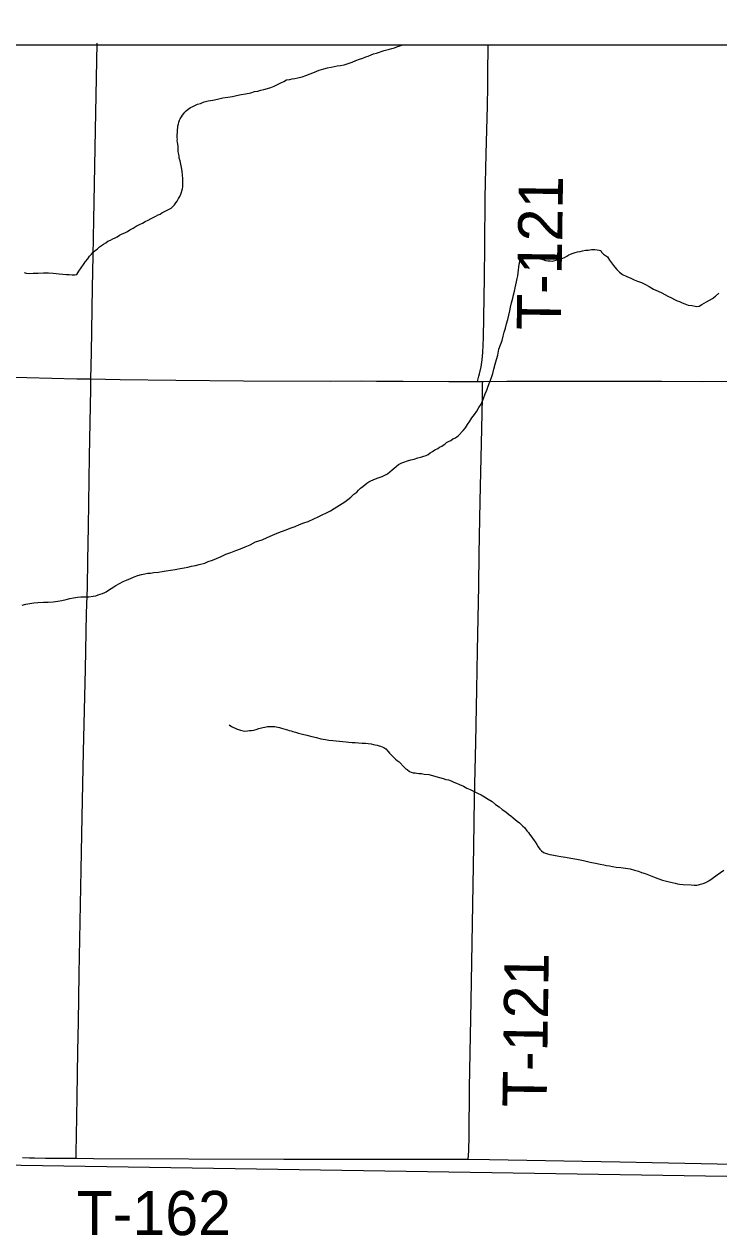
# Model space of a CAD drawing. Extents: x 2.1 to 73.9, y 4 to 26.
# Drawn here: x 44.021 to 44.468, y 18.775 to 19.554 of the extents above; entities that cross this region are included whole.
import ezdxf

# ---------------------------------------------------------------- set-up
doc = ezdxf.new("R2010")
doc.units = 0
for name, color, linetype in [('GM_X_Minor_River', 7, 'Continuous'), ('GM_X_Township_Road', 7, 'Continuous'), ('GM_X_Township_Road_Text', 7, 'Continuous'), ('SH_Text', 7, 'Continuous')]:
    doc.layers.add(name, color=color, linetype=linetype)

msp = doc.modelspace()

# ---------------------------------------------------------------- linework, layer by layer
at = {"layer": 'GM_X_Minor_River'}
for points in [[(44.25604, 19.53844), (44.25757, 19.53878), (44.25929, 19.53932), (44.26082, 19.53985), (44.26274, 19.54057), (44.26385, 19.54109), (44.26385, 19.54109)], [(44.11396, 19.4353), (44.11551, 19.43621), (44.11687, 19.43751), (44.11765, 19.43844), (44.11862, 19.43956), (44.11941, 19.44068), (44.1204, 19.44237), (44.12119, 19.44368), (44.12179, 19.44519), (44.12282, 19.44858), (44.12304, 19.44991), (44.12308, 19.45161), (44.12312, 19.45332), (44.12316, 19.45522), (44.12283, 19.45732), (44.1227, 19.45998), (44.12218, 19.46227), (44.12185, 19.46456), (44.12133, 19.46666), (44.1208, 19.46838), (44.12064, 19.4699), (44.1203, 19.47162), (44.12014, 19.47295), (44.11999, 19.47447), (44.12002, 19.4758), (44.11986, 19.47733), (44.1197, 19.47847), (44.11953, 19.47961), (44.11956, 19.48056), (44.11939, 19.48151), (44.11944, 19.4836), (44.11965, 19.48474), (44.11968, 19.48588), (44.1197, 19.48682), (44.11992, 19.48796), (44.11994, 19.4891), (44.12035, 19.49023), (44.12057, 19.49155), (44.12097, 19.49268), (44.12138, 19.49362), (44.12217, 19.49494), (44.12295, 19.49606), (44.12373, 19.49699), (44.12432, 19.49793), (44.1253, 19.49885), (44.12646, 19.49978), (44.128, 19.50088), (44.12916, 19.50143), (44.13243, 19.50306), (44.13453, 19.50358), (44.13683, 19.50448), (44.13932, 19.50518), (44.14237, 19.50568), (44.14543, 19.50637), (44.14887, 19.50706), (44.15211, 19.50755), (44.15497, 19.50806), (44.15765, 19.50857), (44.16051, 19.50926), (44.16338, 19.50977), (44.16681, 19.51045), (44.16911, 19.51116), (44.1714, 19.51148), (44.17331, 19.51201), (44.17523, 19.51254), (44.17752, 19.51306), (44.17963, 19.51377), (44.18174, 19.51467), (44.18404, 19.51576), (44.18616, 19.51685), (44.18808, 19.51775), (44.18981, 19.51867), (44.19191, 19.519), (44.19344, 19.51934), (44.19515, 19.51949), (44.19707, 19.52002), (44.19974, 19.52072), (44.20224, 19.52161), (44.20492, 19.5225), (44.2078, 19.52358), (44.21086, 19.52484), (44.21374, 19.52572), (44.21603, 19.52643), (44.21852, 19.52694), (44.22043, 19.52728), (44.22233, 19.52762), (44.22443, 19.52795), (44.22692, 19.52846), (44.2294, 19.52917), (44.2319, 19.53006), (44.23439, 19.53114), (44.23669, 19.53204), (44.2388, 19.53275), (44.24072, 19.53347), (44.24225, 19.534), (44.24417, 19.53472), (44.24571, 19.53545), (44.24762, 19.53597), (44.2526, 19.53757), (44.25432, 19.53791), (44.25604, 19.53844)], [(44.02103, 19.39486), (44.02235, 19.39445), (44.02425, 19.39421), (44.02692, 19.39434), (44.02996, 19.39446), (44.03338, 19.39458), (44.03661, 19.39451), (44.03965, 19.39444), (44.04345, 19.39397), (44.04591, 19.39372), (44.048, 19.39349), (44.0499, 19.39344), (44.05199, 19.3934), (44.0537, 19.39336), (44.05484, 19.39352), (44.05622, 19.39558), (44.05779, 19.39782), (44.05917, 19.39988), (44.06055, 19.40194), (44.06192, 19.40362), (44.06309, 19.4053), (44.06426, 19.4066), (44.06543, 19.40791), (44.06679, 19.40902), (44.06815, 19.41012), (44.0695, 19.41123), (44.07066, 19.41216), (44.07202, 19.41308), (44.07356, 19.41399), (44.07491, 19.41491), (44.07645, 19.41563), (44.07799, 19.41655), (44.07952, 19.41708), (44.08087, 19.41781), (44.08241, 19.41873), (44.08414, 19.41964), (44.08587, 19.42036), (44.08741, 19.42127), (44.08895, 19.42219), (44.09107, 19.42328), (44.093, 19.42457), (44.09512, 19.42566), (44.09704, 19.42656), (44.09877, 19.42766), (44.10069, 19.42857), (44.10262, 19.42948), (44.10435, 19.43039), (44.10569, 19.43112), (44.10723, 19.43184), (44.10858, 19.43238), (44.10954, 19.43312), (44.11089, 19.43385), (44.11204, 19.43439), (44.11301, 19.43494), (44.11396, 19.4353)], [(44.26271, 19.27183), (44.26386, 19.27238), (44.26521, 19.27292), (44.26751, 19.27362), (44.2698, 19.27433), (44.27191, 19.27486), (44.2742, 19.27556), (44.27612, 19.27609), (44.27803, 19.27662), (44.27956, 19.27715), (44.28091, 19.27788), (44.28226, 19.2788), (44.28361, 19.27972), (44.28516, 19.28082), (44.28708, 19.28173), (44.28824, 19.28246), (44.28958, 19.28319), (44.29055, 19.28374), (44.29151, 19.28448), (44.29268, 19.2854), (44.29402, 19.28613), (44.29537, 19.28686), (44.29672, 19.28778), (44.29807, 19.28832), (44.29922, 19.28905), (44.30038, 19.28998), (44.3035, 19.29332), (44.30487, 19.295), (44.30625, 19.29706), (44.30763, 19.29912), (44.30901, 19.30137), (44.31058, 19.30342), (44.31215, 19.30566), (44.31353, 19.30791), (44.31491, 19.31016), (44.31651, 19.31373), (44.31753, 19.31675), (44.31854, 19.31919), (44.31954, 19.32164), (44.32056, 19.32447), (44.32157, 19.32729), (44.32239, 19.32993), (44.32322, 19.33276), (44.32405, 19.33578), (44.32488, 19.3388), (44.3257, 19.34163), (44.32636, 19.34542), (44.32737, 19.34824), (44.32839, 19.35107), (44.32902, 19.3539), (44.32984, 19.35654), (44.33066, 19.35899), (44.33129, 19.36183), (44.33212, 19.36466), (44.33275, 19.36749), (44.33338, 19.37014), (44.33382, 19.3726), (44.33445, 19.37524), (44.33528, 19.37826), (44.33571, 19.38053), (44.33633, 19.38279), (44.33676, 19.38487), (44.33719, 19.38695), (44.33761, 19.38884), (44.33804, 19.39092), (44.33846, 19.39262), (44.33869, 19.39452), (44.33893, 19.3966), (44.33916, 19.3983), (44.33939, 19.4002), (44.3398, 19.40171), (44.34003, 19.40322), (44.34043, 19.40435), (44.34141, 19.40547), (44.34294, 19.40601), (44.34389, 19.40579), (44.34522, 19.40557), (44.34654, 19.40536), (44.34787, 19.40514), (44.349, 19.40492), (44.35032, 19.40451), (44.35165, 19.4041), (44.35316, 19.40369), (44.35466, 19.40308), (44.35636, 19.40247), (44.35788, 19.40225), (44.3594, 19.40222), (44.36073, 19.40219), (44.36244, 19.40253), (44.36417, 19.40306), (44.36589, 19.40359), (44.36742, 19.40412), (44.36857, 19.40448), (44.37011, 19.40539), (44.37127, 19.40613), (44.37242, 19.40667), (44.37415, 19.4072), (44.37549, 19.40774), (44.37702, 19.40809), (44.37855, 19.40843), (44.38008, 19.40878)], [(44.38008, 19.40878), (44.38199, 19.40911), (44.38389, 19.40926), (44.38599, 19.40959), (44.38808, 19.40954), (44.38959, 19.40932), (44.39092, 19.4091), (44.39187, 19.40889), (44.39241, 19.40793), (44.39371, 19.40657), (44.39484, 19.40578), (44.39615, 19.4048), (44.39743, 19.40269), (44.40001, 19.3994), (44.40094, 19.39824), (44.40223, 19.39669), (44.40391, 19.39513), (44.40597, 19.39357), (44.40859, 19.39218), (44.41123, 19.39117), (44.41349, 19.39017), (44.41556, 19.38917), (44.4182, 19.38835), (44.42065, 19.38716), (44.42309, 19.38578), (44.4259, 19.38419), (44.42872, 19.3828), (44.43117, 19.3818), (44.43305, 19.38061), (44.43511, 19.37962), (44.43737, 19.37862), (44.43925, 19.37743), (44.44094, 19.37664), (44.44264, 19.37622), (44.44433, 19.37542), (44.44603, 19.37462), (44.4481, 19.37382), (44.45037, 19.37358), (44.45151, 19.37336), (44.45378, 19.37293), (44.45512, 19.37309), (44.45685, 19.37419), (44.45839, 19.3751), (44.45994, 19.37602), (44.46186, 19.37693), (44.46378, 19.37802), (44.46572, 19.3795), (44.46785, 19.38154)], [(44.02208, 19.18155), (44.02475, 19.18187), (44.02724, 19.18239), (44.02991, 19.1827), (44.03352, 19.18281), (44.03656, 19.18293), (44.03961, 19.18305), (44.04266, 19.18356), (44.04533, 19.18387), (44.04801, 19.18457), (44.05049, 19.18509), (44.05278, 19.18561), (44.05527, 19.18612), (44.05755, 19.18626), (44.06021, 19.1862), (44.06269, 19.18633), (44.06535, 19.18665), (44.06707, 19.18699), (44.06861, 19.18753), (44.06994, 19.18788), (44.07148, 19.18841), (44.07282, 19.18895), (44.07378, 19.1895), (44.07533, 19.1906), (44.07707, 19.1917), (44.07861, 19.19262), (44.07996, 19.19354), (44.08477, 19.19609), (44.08688, 19.19699), (44.08938, 19.19807), (44.09187, 19.19916), (44.09417, 19.20005), (44.09647, 19.20057), (44.09857, 19.20109), (44.10048, 19.20143), (44.10238, 19.20158), (44.10448, 19.20191), (44.10734, 19.20203), (44.10982, 19.20255), (44.1123, 19.20287), (44.11516, 19.20338), (44.11821, 19.20388), (44.12127, 19.20438), (44.12394, 19.20489), (44.12623, 19.20541), (44.12871, 19.20592), (44.1312, 19.20643), (44.13369, 19.20714), (44.13713, 19.20801), (44.13943, 19.20891), (44.14211, 19.20979), (44.1448, 19.21087), (44.14768, 19.21214), (44.15075, 19.21359), (44.15401, 19.21484), (44.15708, 19.2161), (44.16015, 19.21717), (44.16322, 19.21843), (44.16629, 19.21969), (44.16975, 19.22152), (44.17416, 19.22294), (44.17742, 19.22438), (44.18068, 19.22583), (44.18375, 19.22709), (44.18664, 19.22835), (44.18951, 19.22943), (44.1922, 19.2305), (44.19526, 19.23157), (44.19814, 19.23284), (44.20083, 19.23392), (44.2037, 19.2348), (44.20735, 19.23643), (44.21004, 19.2377), (44.21273, 19.23897), (44.21542, 19.24024), (44.21811, 19.2415), (44.22042, 19.24297), (44.22718, 19.24738), (44.2293, 19.24885), (44.23124, 19.25032), (44.23299, 19.25218), (44.23492, 19.25366), (44.23609, 19.25477), (44.23745, 19.25607), (44.23881, 19.25718), (44.24016, 19.25829), (44.24152, 19.2594), (44.24268, 19.26013), (44.24402, 19.26086), (44.24556, 19.26159), (44.24709, 19.26212), (44.24882, 19.26284), (44.25131, 19.26355), (44.25304, 19.26446), (44.25477, 19.26537), (44.25632, 19.26666), (44.25768, 19.26796), (44.25904, 19.26907), (44.2602, 19.26999), (44.26175, 19.27129), (44.26271, 19.27183)], [(44.01979, 19.18084), (44.02208, 19.18155)], [(44.15283, 19.10395), (44.15432, 19.10278), (44.15752, 19.10138), (44.16017, 19.10056), (44.16187, 19.10014), (44.163, 19.09993), (44.16472, 19.10008), (44.16586, 19.10024), (44.1672, 19.1004), (44.16872, 19.10056), (44.17025, 19.1009), (44.17198, 19.10162), (44.17446, 19.10213), (44.1758, 19.10248), (44.17752, 19.10283), (44.18227, 19.10291), (44.18322, 19.1027), (44.18416, 19.10249), (44.1853, 19.10227), (44.18662, 19.10186), (44.18794, 19.10145), (44.18945, 19.10085), (44.19039, 19.10064), (44.19153, 19.10023), (44.19266, 19.10001), (44.19379, 19.09961), (44.19549, 19.09919), (44.19757, 19.09857), (44.20003, 19.09795), (44.20287, 19.09732), (44.20608, 19.09648), (44.20911, 19.09584), (44.21175, 19.09502), (44.21478, 19.09458), (44.21705, 19.09415), (44.21952, 19.0939), (44.22179, 19.09366), (44.22388, 19.09342), (44.22596, 19.09318), (44.22805, 19.09295), (44.22995, 19.09271), (44.23204, 19.09267), (44.23394, 19.09262), (44.23602, 19.09239), (44.23849, 19.09214), (44.24058, 19.09209), (44.24228, 19.09187), (44.24418, 19.09163), (44.24569, 19.09122), (44.24683, 19.091), (44.24815, 19.09078), (44.24928, 19.09038), (44.25023, 19.09017), (44.25136, 19.08976), (44.2523, 19.08936), (44.25361, 19.08857), (44.2551, 19.08683), (44.25602, 19.08567), (44.25732, 19.0845), (44.25862, 19.08314), (44.25993, 19.08197), (44.26105, 19.081), (44.26217, 19.08021), (44.26551, 19.07672), (44.26644, 19.07575), (44.26738, 19.07515), (44.26887, 19.07398), (44.27, 19.07358), (44.27114, 19.07317), (44.27247, 19.07314), (44.2736, 19.07293), (44.27493, 19.07271), (44.27664, 19.07267), (44.27834, 19.07225), (44.28137, 19.07199), (44.28364, 19.07137), (44.28591, 19.07075), (44.28818, 19.07013), (44.29044, 19.06951), (44.29233, 19.06889), (44.29403, 19.06848), (44.29573, 19.06787), (44.29742, 19.06707), (44.29912, 19.06646), (44.301, 19.06566), (44.30364, 19.06446), (44.3057, 19.06327), (44.30796, 19.06227), (44.3104, 19.06108), (44.31266, 19.06008), (44.31492, 19.05889), (44.31717, 19.0577), (44.31942, 19.05613), (44.32204, 19.05455), (44.32428, 19.05279), (44.32653, 19.05122), (44.32858, 19.04946), (44.33083, 19.04789), (44.33251, 19.04653), (44.334, 19.04535), (44.33549, 19.04418)], [(44.33549, 19.04418), (44.3368, 19.04301), (44.33811, 19.04203), (44.3396, 19.04086), (44.34072, 19.03988), (44.34183, 19.03872), (44.34277, 19.03794), (44.34443, 19.03581), (44.34535, 19.03465), (44.34609, 19.03368), (44.34683, 19.03253), (44.34904, 19.02963), (44.34978, 19.02866), (44.35088, 19.02693), (44.35161, 19.02558), (44.35272, 19.02404), (44.35383, 19.02287), (44.35514, 19.02189), (44.35627, 19.02149), (44.35759, 19.02108), (44.3591, 19.02066), (44.36175, 19.02003), (44.36384, 19.0198), (44.3663, 19.01936), (44.36914, 19.01892), (44.37255, 19.01827), (44.37652, 19.01761), (44.38088, 19.01675), (44.38504, 19.01571), (44.38844, 19.01506), (44.39147, 19.01443), (44.39393, 19.01399), (44.39563, 19.01357), (44.39753, 19.01334), (44.39942, 19.01292), (44.40188, 19.01248), (44.40473, 19.01223), (44.40776, 19.01178), (44.41079, 19.01133), (44.41362, 19.01051), (44.41608, 19.00988), (44.41815, 19.00908), (44.42042, 19.00827), (44.42268, 19.00745), (44.42588, 19.00624), (44.42852, 19.00504), (44.43154, 19.00403), (44.43494, 19.00319), (44.43778, 19.00256), (44.43986, 19.00213), (44.44118, 19.00172), (44.4425, 19.0015), (44.44497, 19.00125), (44.4501, 19.00114), (44.452, 19.00091), (44.45371, 19.00087), (44.45485, 19.00103), (44.456, 19.00139), (44.45772, 19.00192), (44.45945, 19.00264), (44.46137, 19.00354), (44.4635, 19.00521), (44.46678, 19.00741), (44.47103, 19.01054)], [(43.5373, 18.82828), (44.59696, 18.81169)]]:
    msp.add_lwpolyline(points, dxfattribs=at)
at = {"layer": 'GM_X_Township_Road'}
msp.add_line((44.31266, 19.32483), (44.31594, 19.32483), dxfattribs=at)
for points in [[(44.06396, 19.32634), (44.06427, 19.34328), (44.06506, 19.38525), (44.06548, 19.40545), (44.06588, 19.42877), (44.067, 19.48627), (44.06791, 19.54223)], [(44.31266, 19.32483), (44.31347, 19.32808), (44.31385, 19.32959), (44.3149, 19.33413), (44.31559, 19.33875), (44.316, 19.34339), (44.31643, 19.35272), (44.3171, 19.39162), (44.31723, 19.41185), (44.31759, 19.44296), (44.31827, 19.47097), (44.31898, 19.50208), (44.31917, 19.51452), (44.31922, 19.5223), (44.31946, 19.54109)], [(43.76276, 19.33357), (43.76737, 19.33351), (43.79689, 19.33273), (43.81243, 19.33223), (43.82797, 19.33198), (43.87615, 19.3309), (43.92122, 19.32996), (43.97095, 19.32852), (44.00669, 19.32764), (44.05487, 19.32655), (44.06396, 19.32634)], [(44.06172, 19.19252), (44.062, 19.20962), (44.06232, 19.23138), (44.063, 19.27645), (44.06385, 19.31997), (44.06396, 19.32634)], [(44.06396, 19.32634), (44.08284, 19.32593), (44.1186, 19.32562), (44.16212, 19.32523), (44.21808, 19.32489), (44.23829, 19.32509), (44.24761, 19.32502), (44.26471, 19.3249), (44.29425, 19.32479), (44.31266, 19.32483)], [(44.30668, 18.82454), (44.30682, 18.82704), (44.307, 18.83014), (44.30721, 18.83945), (44.30755, 18.87051), (44.30846, 18.9264), (44.31026, 19.02576), (44.31078, 19.05681), (44.31151, 19.09252), (44.31225, 19.12667), (44.31258, 19.15151), (44.3134, 19.19343), (44.31375, 19.21361), (44.31437, 19.24777), (44.31531, 19.29434), (44.31586, 19.31452), (44.31592, 19.32298), (44.31594, 19.32483)], [(44.31594, 19.32483), (44.33156, 19.32486), (44.3642, 19.32497), (44.39374, 19.32491), (44.43105, 19.32496), (44.45747, 19.3248), (44.56163, 19.32486), (44.56658, 19.3248)], [(44.05442, 18.82518), (44.05446, 18.82884), (44.05458, 18.83972), (44.05503, 18.86458), (44.05557, 18.89411), (44.05604, 18.91277), (44.05646, 18.94385), (44.05779, 19.01068), (44.05843, 19.04488), (44.05926, 19.08684), (44.06052, 19.13968), (44.06112, 19.17543), (44.06172, 19.19252)], [(44.02004, 18.82565), (44.02447, 18.82552), (44.02776, 18.82539), (44.03476, 18.82533), (44.04884, 18.8252), (44.05442, 18.82518)], [(44.05442, 18.82518), (44.06561, 18.82513), (44.18808, 18.82465), (44.21452, 18.82472), (44.25806, 18.8247), (44.3016, 18.8246), (44.30668, 18.82454)], [(44.30668, 18.82454), (44.32026, 18.82437), (44.40421, 18.82287), (44.47728, 18.82134), (44.52003, 18.8203), (44.52336, 18.82014), (44.52498, 18.81984), (44.52668, 18.8193), (44.52751, 18.81903)]]:
    msp.add_lwpolyline(points, dxfattribs=at)
at = {"layer": 'SH_Text'}
msp.add_lwpolyline([(45.17346, 19.54109), (43.56201, 19.54109), (43.56201, 20.16526), (45.17346, 20.16526)], close=True, dxfattribs=at)

# ---------------------------------------------------------------- texts
at = {"layer": 'GM_X_Township_Road_Text'}
for s, rotation, p in [('T-121', 89.15922, (44.36621, 19.35757)), ('T-121', 89.15453, (44.35704, 18.85789)), ('T-162', 0.00001, (44.05482, 18.77578))]:
    msp.add_text(s, height=0.028409, rotation=rotation, dxfattribs=at).set_placement(p)

doc.saveas('drawing.dxf')
